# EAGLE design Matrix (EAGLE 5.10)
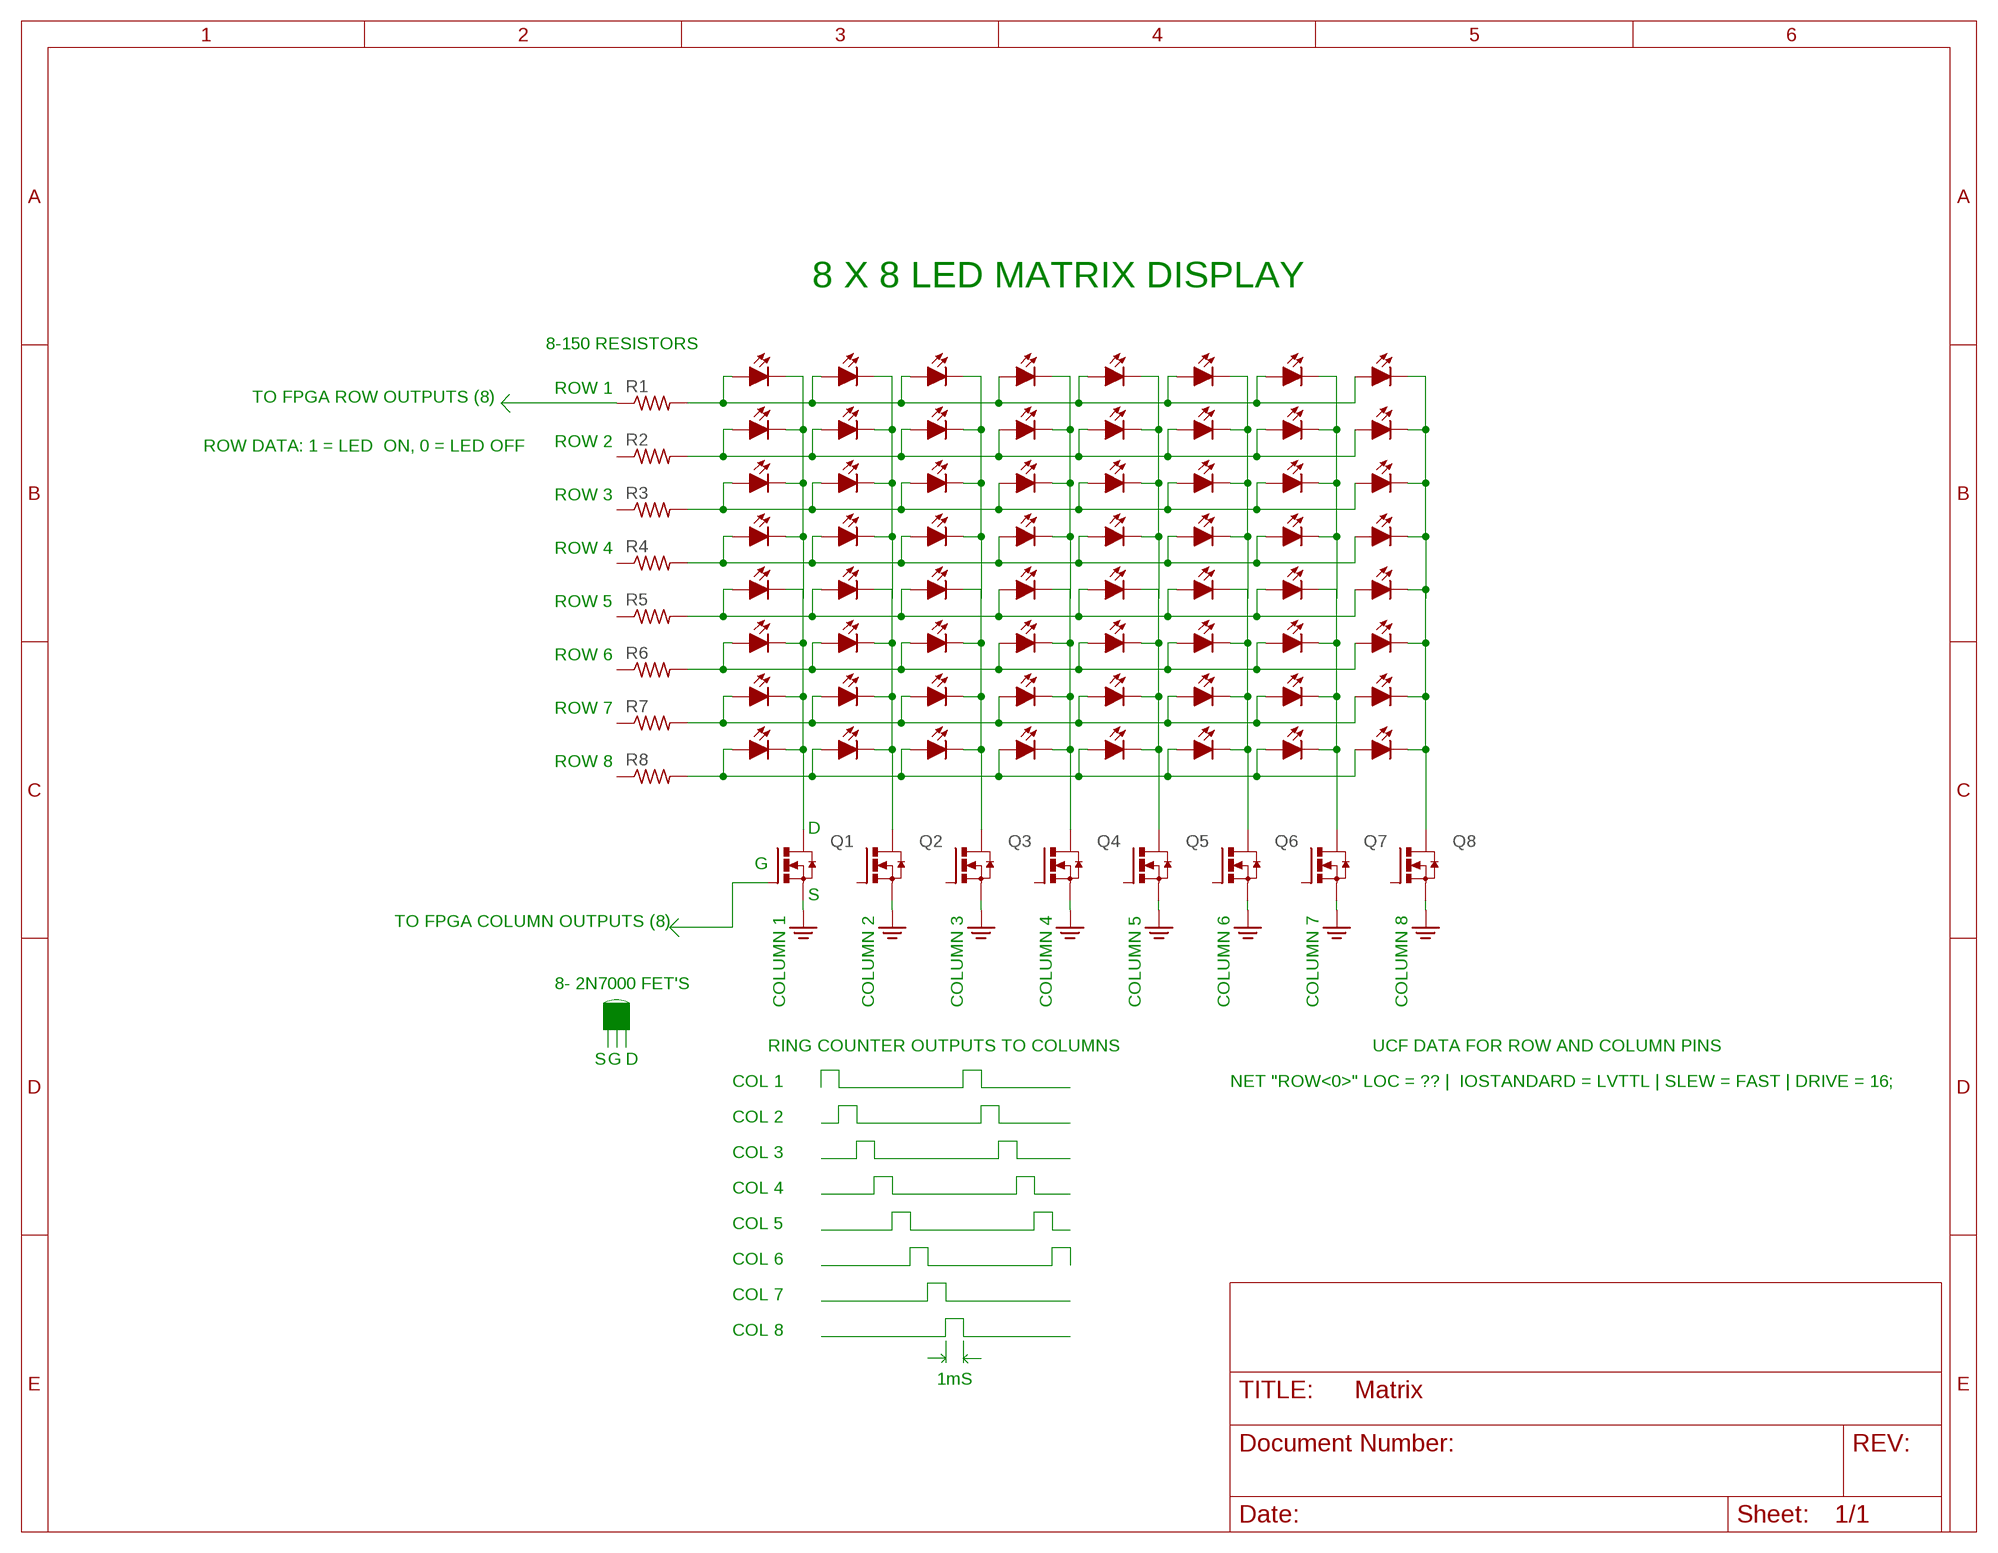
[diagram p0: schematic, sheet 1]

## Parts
D1  LED_ANGLE  [RES_400]
D2  LED_ANGLE  [RES_400]
D3  LED_ANGLE  [RES_400]
D4  LED_ANGLE  [RES_400]
D5  LED_ANGLE  [RES_400]
D6  LED_ANGLE  [RES_400]
D7  LED_ANGLE  [RES_400]
D8  LED_ANGLE  [RES_400]
D9  LED_ANGLE  [RES_400]
D10  LED_ANGLE  [RES_400]
D11  LED_ANGLE  [RES_400]
D12  LED_ANGLE  [RES_400]
D13  LED_ANGLE  [RES_400]
D14  LED_ANGLE  [RES_400]
D15  LED_ANGLE  [RES_400]
D16  LED_ANGLE  [RES_400]
D17  LED_ANGLE  [RES_400]
D18  LED_ANGLE  [RES_400]
D19  LED_ANGLE  [RES_400]
D20  LED_ANGLE  [RES_400]
D21  LED_ANGLE  [RES_400]
D22  LED_ANGLE  [RES_400]
D23  LED_ANGLE  [RES_400]
D24  LED_ANGLE  [RES_400]
D25  LED_ANGLE  [RES_400]
D26  LED_ANGLE  [RES_400]
D27  LED_ANGLE  [RES_400]
D28  LED_ANGLE  [RES_400]
D29  LED_ANGLE  [RES_400]
D30  LED_ANGLE  [RES_400]
D31  LED_ANGLE  [RES_400]
D32  LED_ANGLE  [RES_400]
D33  LED_ANGLE  [RES_400]
D34  LED_ANGLE  [RES_400]
D35  LED_ANGLE  [RES_400]
D36  LED_ANGLE  [RES_400]
D37  LED_ANGLE  [RES_400]
D38  LED_ANGLE  [RES_400]
D39  LED_ANGLE  [RES_400]
D40  LED_ANGLE  [RES_400]
D41  LED_ANGLE  [RES_400]
D42  LED_ANGLE  [RES_400]
D43  LED_ANGLE  [RES_400]
D44  LED_ANGLE  [RES_400]
D45  LED_ANGLE  [RES_400]
D46  LED_ANGLE  [RES_400]
D47  LED_ANGLE  [RES_400]
D48  LED_ANGLE  [RES_400]
D49  LED_ANGLE  [RES_400]
D50  LED_ANGLE  [RES_400]
D51  LED_ANGLE  [RES_400]
D52  LED_ANGLE  [RES_400]
D53  LED_ANGLE  [RES_400]
D54  LED_ANGLE  [RES_400]
D55  LED_ANGLE  [RES_400]
D56  LED_ANGLE  [RES_400]
D57  LED_ANGLE  [RES_400]
D58  LED_ANGLE  [RES_400]
D59  LED_ANGLE  [RES_400]
D60  LED_ANGLE  [RES_400]
D61  LED_ANGLE  [RES_400]
D62  LED_ANGLE  [RES_400]
D63  LED_ANGLE  [RES_400]
D64  LED_ANGLE  [RES_400]
Q1  N-HEXFET_SOT323-IRLL2705  [SOT223]
Q2  N-HEXFET_SOT323-IRLL2705  [SOT223]
Q3  N-HEXFET_SOT323-IRLL2705  [SOT223]
Q4  N-HEXFET_SOT323-IRLL2705  [SOT223]
Q5  N-HEXFET_SOT323-IRLL2705  [SOT223]
Q6  N-HEXFET_SOT323-IRLL2705  [SOT223]
Q7  N-HEXFET_SOT323-IRLL2705  [SOT223]
Q8  N-HEXFET_SOT323-IRLL2705  [SOT223]
R1  R-US_0204/2V  [0204V]
R2  R-US_0204/2V  [0204V]
R3  R-US_0204/2V  [0204V]
R4  R-US_0204/2V  [0204V]
R5  R-US_0204/2V  [0204V]
R6  R-US_0204/2V  [0204V]
R7  R-US_0204/2V  [0204V]
R8  R-US_0204/2V  [0204V]

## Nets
N$67: D1.2(C) D5.2(C) D9.2(C) D13.2(C) Q1.4(D)
N$68: D2.2(C) D6.2(C) D10.2(C) D14.2(C) Q2.4(D)
N$69: D3.2(C) D7.2(C) D11.2(C) D15.2(C) Q3.4(D)
N$70: D4.2(C) D8.2(C) D12.2(C) D16.2(C) Q4.4(D)
N$71: R1.1
N$72: Q1.1(G)
N$75: D17.2(C) D21.2(C) D25.2(C) D29.2(C) Q5.4(D)
N$76: D18.2(C) D22.2(C) D26.2(C) D30.2(C) Q6.4(D)
N$77: D19.2(C) D23.2(C) D27.2(C) D31.2(C) Q7.4(D)
N$78: D24.2(C) D28.2(C) D32.2(C) Q8.4(D)
N$79: D1.1(A) D2.1(A) D3.1(A) D4.1(A) D17.1(A) D18.1(A) D19.1(A) D20.1(A) R5.2
N$80: D5.1(A) D6.1(A) D7.1(A) D8.1(A) D21.1(A) D22.1(A) D23.1(A) D24.1(A) R6.2
N$81: D9.1(A) D10.1(A) D11.1(A) D12.1(A) D25.1(A) D26.1(A) D27.1(A) D28.1(A) R7.2
N$82: D13.1(A) D14.1(A) D15.1(A) D16.1(A) D29.1(A) D30.1(A) D31.1(A) D32.1(A) R8.2
N$83: D33.2(C) D37.2(C) D41.2(C) D45.2(C)
N$84: D34.2(C) D38.2(C) D42.2(C) D46.2(C)
N$85: D35.2(C) D39.2(C) D43.2(C) D47.2(C)
N$86: D36.2(C) D40.2(C) D44.2(C) D48.2(C)
N$91: D49.2(C) D53.2(C) D57.2(C) D61.2(C)
N$92: D50.2(C) D54.2(C) D58.2(C) D62.2(C)
N$93: D51.2(C) D55.2(C) D59.2(C) D63.2(C)
N$94: D20.2(C) D52.2(C) D56.2(C) D60.2(C) D64.2(C)
N$95: D33.1(A) D34.1(A) D35.1(A) D36.1(A) D49.1(A) D50.1(A) D51.1(A) D52.1(A) R1.2
N$96: D37.1(A) D38.1(A) D39.1(A) D40.1(A) D53.1(A) D54.1(A) D55.1(A) D56.1(A) R2.2
N$97: D41.1(A) D42.1(A) D43.1(A) D44.1(A) D57.1(A) D58.1(A) D59.1(A) D60.1(A) R3.2
N$98: D45.1(A) D46.1(A) D47.1(A) D48.1(A) D61.1(A) D62.1(A) D63.1(A) D64.1(A) R4.2
PE: Q1.3(S) Q2.3(S) Q3.3(S) Q4.3(S) Q5.3(S) Q6.3(S) Q7.3(S) Q8.3(S)
Unconnected: Q2.1(G) Q3.1(G) Q4.1(G) Q5.1(G) Q6.1(G) Q7.1(G) Q8.1(G) R2.1 R3.1 R4.1 R5.1 R6.1 R7.1 R8.1

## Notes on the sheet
- 8 X 8 LED MATRIX DISPLAY
- 8-150 RESISTORS
- ROW 1
- TO FPGA ROW OUTPUTS (8)
- ROW DATA: 1 = LED  ON, 0 = LED OFF | ROW 2
- ROW 3
- ROW 4
- ROW 5
- ROW 6
- ROW 7
- ROW 8
- D
- G
- S
- TO FPGA COLUMN OUTPUTS (8)
- 8- 2N7000 FET'S
- COLUMN 1 | COLUMN 2 | COLUMN 3 | COLUMN 4 | COLUMN 5 | COLUMN 6 | COLUMN 7 | COLUMN 8
- RING COUNTER OUTPUTS TO COLUMNS | UCF DATA FOR ROW AND COLUMN PINS
- S | G | D
- COL 1 | NET "ROW<0>" LOC = ?? |  IOSTANDARD = LVTTL | SLEW = FAST | DRIVE = 16;
- COL 2
- COL 3
- COL 4
- COL 5
- COL 6
- COL 7
- COL 8
- 1mS

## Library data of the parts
D1-D64 = led_matrix:LED_ANGLE
Q1-Q8 = transistor-power:N-HEXFET_?-*: HEXFET® Power MOSFET
R1-R8 = rcl:R-US_: RESISTOR, American symbol

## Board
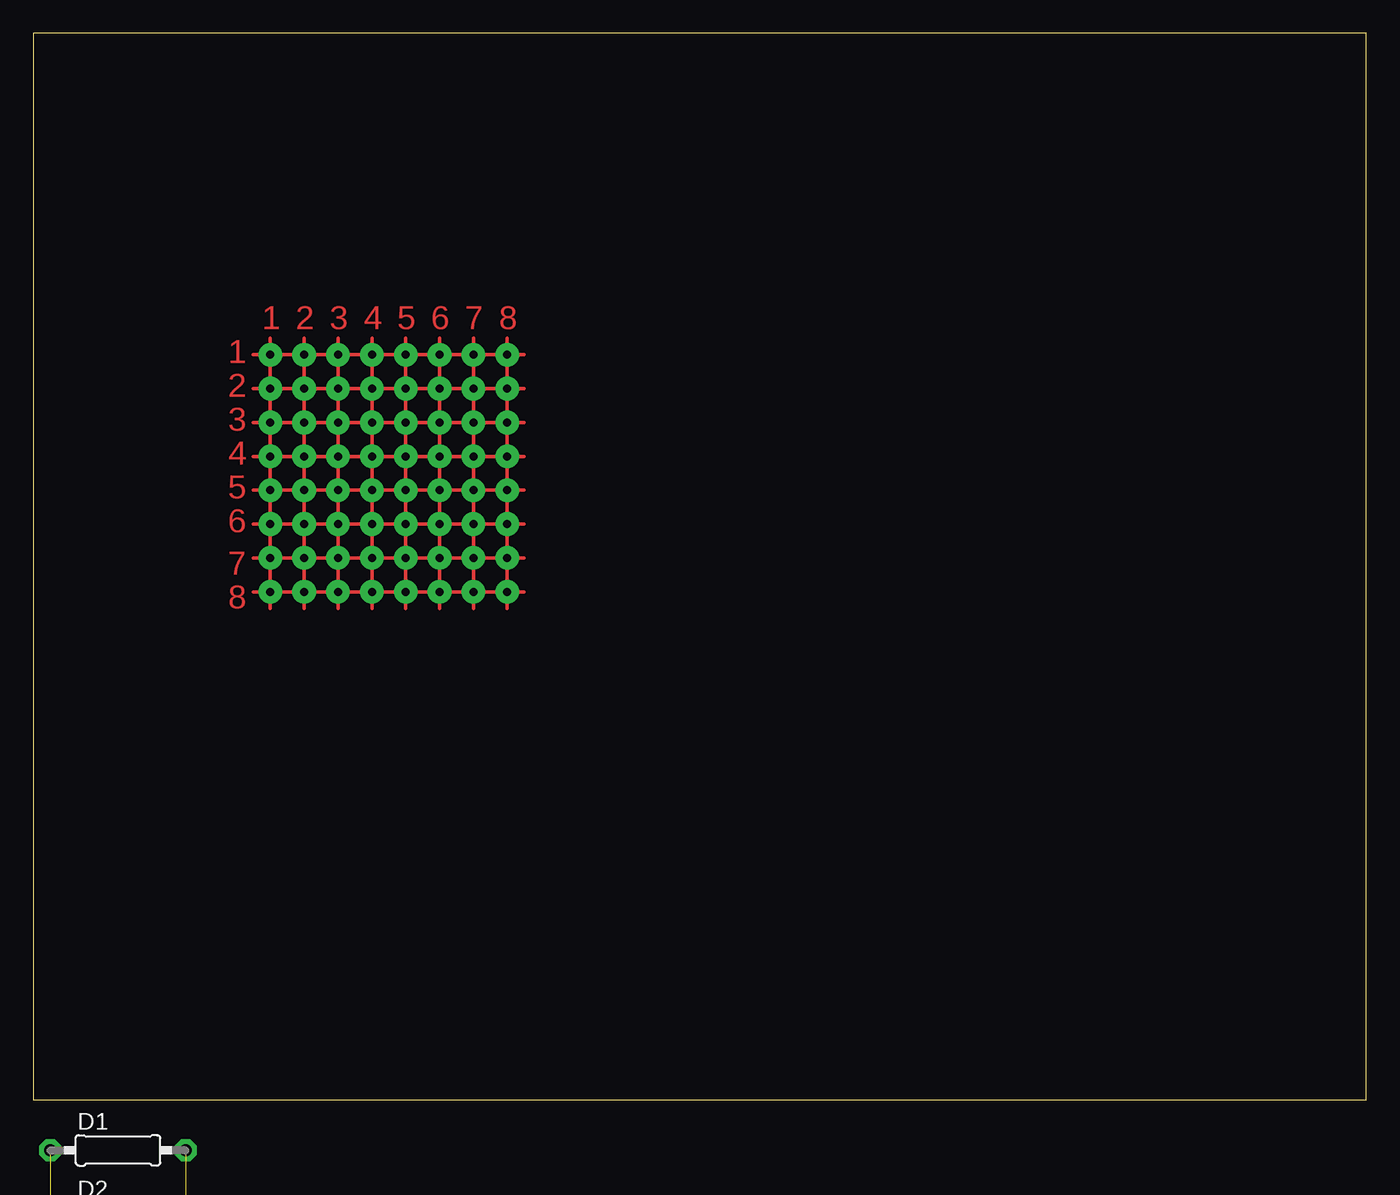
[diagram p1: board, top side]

Size 100 x 80 mm. Coordinates in mm from the lower left corner, seen from the top.
Outline: 0,0 100,0 100,80 0,80 0,0
Copper layers (1*16): Top 0.035mm / dielectric 1.5mm / Bottom 0.035mm
Design rules "default": minimum track width 10mil, minimum drill 24mil, track to track 8mil, track to pad 8mil, pad to pad 8mil, via to via 8mil, smd to smd 8mil, copper to edge 40mil, drill to drill 8mil, minimum pad ring 10mil, minimum via ring 8mil, stop-mask expansion 4mil, vias tented up to drill 0mil, thermal gap 10mil

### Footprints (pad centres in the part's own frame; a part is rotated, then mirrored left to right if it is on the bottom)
RES_400 = drill 0.9 pad 1.676 octagon: 1 0,0; 2 10.16,0
SOT223 = smd 1.219 x 2.235: 1 -2.311,-3.099; 2 0,-3.099; 3 2.311,-3.099 | smd 3.6 x 2.2: 4 0,3.099
0204V = drill 0.813 octagon: 1 -1.27,0; 2 1.27,0

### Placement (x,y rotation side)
D1  not placed on the board
D2  not placed on the board
D3  not placed on the board
D4  not placed on the board
D5  not placed on the board
D6  not placed on the board
D7  not placed on the board
D8  not placed on the board
D9  not placed on the board
D10  not placed on the board
D11  not placed on the board
D12  not placed on the board
D13  not placed on the board
D14  not placed on the board
D15  not placed on the board
D16  not placed on the board
D17  not placed on the board
D18  not placed on the board
D19  not placed on the board
D20  not placed on the board
D21  not placed on the board
D22  not placed on the board
D23  not placed on the board
D24  not placed on the board
D25  not placed on the board
D26  not placed on the board
D27  not placed on the board
D28  not placed on the board
D29  not placed on the board
D30  not placed on the board
D31  not placed on the board
D32  not placed on the board
D33  not placed on the board
D34  not placed on the board
D35  not placed on the board
D36  not placed on the board
D37  not placed on the board
D38  not placed on the board
D39  not placed on the board
D40  not placed on the board
D41  not placed on the board
D42  not placed on the board
D43  not placed on the board
D44  not placed on the board
D45  not placed on the board
D46  not placed on the board
D47  not placed on the board
D48  not placed on the board
D49  not placed on the board
D50  not placed on the board
D51  not placed on the board
D52  not placed on the board
D53  not placed on the board
D54  not placed on the board
D55  not placed on the board
D56  not placed on the board
D57  not placed on the board
D58  not placed on the board
D59  not placed on the board
D60  not placed on the board
D61  not placed on the board
D62  not placed on the board
D63  not placed on the board
D64  not placed on the board
Q1  not placed on the board
Q2  not placed on the board
Q3  not placed on the board
Q4  not placed on the board
Q5  not placed on the board
Q6  not placed on the board
Q7  not placed on the board
Q8  not placed on the board
R1  not placed on the board
R2  not placed on the board
R3  not placed on the board
R4  not placed on the board
R5  not placed on the board
R6  not placed on the board
R7  not placed on the board
R8  not placed on the board

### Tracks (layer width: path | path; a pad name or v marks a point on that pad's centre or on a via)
N$1  (via drill 0.6 pad 1.78)
  other vias: 17.78,55.88
N$2  (via drill 0.6 pad 1.78)
  other vias: 20.32,55.88
N$3  (via drill 0.6 pad 1.78)
  other vias: 22.86,55.88
N$4  (via drill 0.6 pad 1.78)
  other vias: 25.4,55.88
N$5  (via drill 0.6 pad 1.78)
  other vias: 27.94,55.88
N$6  (via drill 0.6 pad 1.78)
  other vias: 30.48,55.88
N$7  (via drill 0.6 pad 1.78)
  other vias: 33.02,55.88
N$8  (via drill 0.6 pad 1.78)
  other vias: 35.56,55.88
N$9  (via drill 0.6 pad 1.78)
  other vias: 17.78,53.34
N$10  (via drill 0.6 pad 1.78)
  other vias: 20.32,53.34
N$11  (via drill 0.6 pad 1.78)
  other vias: 22.86,53.34
N$12  (via drill 0.6 pad 1.78)
  other vias: 25.4,53.34
N$13  (via drill 0.6 pad 1.78)
  other vias: 27.94,53.34
N$14  (via drill 0.6 pad 1.78)
  other vias: 30.48,53.34
N$15  (via drill 0.6 pad 1.78)
  other vias: 33.02,53.34
N$16  (via drill 0.6 pad 1.78)
  other vias: 35.56,53.34
N$17  (via drill 0.6 pad 1.78)
  other vias: 17.78,50.8
N$18  (via drill 0.6 pad 1.78)
  other vias: 20.32,50.8
N$19  (via drill 0.6 pad 1.78)
  other vias: 22.86,50.8
N$20  (via drill 0.6 pad 1.78)
  other vias: 25.4,50.8
N$21  (via drill 0.6 pad 1.78)
  other vias: 27.94,50.8
N$22  (via drill 0.6 pad 1.78)
  other vias: 30.48,50.8
N$23  (via drill 0.6 pad 1.78)
  other vias: 33.02,50.8
N$24  (via drill 0.6 pad 1.78)
  other vias: 35.56,50.8
N$25  (via drill 0.6 pad 1.78)
  other vias: 17.78,48.26
N$26  (via drill 0.6 pad 1.78)
  other vias: 20.32,48.26
N$27  (via drill 0.6 pad 1.78)
  other vias: 22.86,48.26
N$28  (via drill 0.6 pad 1.78)
  other vias: 25.4,48.26
N$29  (via drill 0.6 pad 1.78)
  other vias: 27.94,48.26
N$30  (via drill 0.6 pad 1.78)
  other vias: 30.48,48.26
N$31  (via drill 0.6 pad 1.78)
  other vias: 33.02,48.26
N$32  (via drill 0.6 pad 1.78)
  other vias: 35.56,48.26
N$33  (via drill 0.6 pad 1.78)
  other vias: 17.78,45.72
N$34  (via drill 0.6 pad 1.78)
  other vias: 20.32,45.72
N$35  (via drill 0.6 pad 1.78)
  other vias: 22.86,45.72
N$36  (via drill 0.6 pad 1.78)
  other vias: 25.4,45.72
N$37  (via drill 0.6 pad 1.78)
  other vias: 27.94,45.72
N$38  (via drill 0.6 pad 1.78)
  other vias: 30.48,45.72
N$39  (via drill 0.6 pad 1.78)
  other vias: 33.02,45.72
N$40  (via drill 0.6 pad 1.78)
  other vias: 35.56,45.72
N$41  (via drill 0.6 pad 1.78)
  other vias: 17.78,43.18
N$42  (via drill 0.6 pad 1.78)
  other vias: 20.32,43.18
N$43  (via drill 0.6 pad 1.78)
  other vias: 22.86,43.18
N$44  (via drill 0.6 pad 1.78)
  other vias: 25.4,43.18
N$45  (via drill 0.6 pad 1.78)
  other vias: 27.94,43.18
N$46  (via drill 0.6 pad 1.78)
  other vias: 30.48,43.18
N$47  (via drill 0.6 pad 1.78)
  other vias: 33.02,43.18
N$48  (via drill 0.6 pad 1.78)
  other vias: 35.56,43.18
N$49  (via drill 0.6 pad 1.78)
  other vias: 17.78,40.64
N$50  (via drill 0.6 pad 1.78)
  other vias: 20.32,40.64
N$51  (via drill 0.6 pad 1.78)
  other vias: 22.86,40.64
N$52  (via drill 0.6 pad 1.78)
  other vias: 25.4,40.64
N$53  (via drill 0.6 pad 1.78)
  other vias: 27.94,40.64
N$54  (via drill 0.6 pad 1.78)
  other vias: 30.48,40.64
N$55  (via drill 0.6 pad 1.78)
  other vias: 33.02,40.64
N$56  (via drill 0.6 pad 1.78)
  other vias: 35.56,40.64
N$57  (via drill 0.6 pad 1.78)
  other vias: 17.78,38.1
N$58  (via drill 0.6 pad 1.78)
  other vias: 20.32,38.1
N$59  (via drill 0.6 pad 1.78)
  other vias: 22.86,38.1
N$60  (via drill 0.6 pad 1.78)
  other vias: 25.4,38.1
N$61  (via drill 0.6 pad 1.78)
  other vias: 27.94,38.1
N$62  (via drill 0.6 pad 1.78)
  other vias: 30.48,38.1
N$63  (via drill 0.6 pad 1.78)
  other vias: 33.02,38.1
N$64  (via drill 0.6 pad 1.78)
  other vias: 35.56,38.1
N$65
  Top 0.254: 16.51,55.88 36.83,55.88 | 16.51,53.34 36.83,53.34 | 16.51,50.8 36.83,50.8 | 16.51,48.26 36.83,48.26 | 16.51,45.72 36.83,45.72 | 16.51,43.18 36.83,43.18 | 16.51,40.64 36.83,40.64 | 16.51,38.1 36.83,38.1
N$66
  Top 0.254: 17.78,57.15 17.78,36.83 | 20.32,57.15 20.32,36.83 | 22.86,57.15 22.86,36.83 | 25.4,57.15 25.4,36.83 | 27.94,57.15 27.94,36.83 | 30.48,57.15 30.48,36.83 | 33.02,57.15 33.02,36.83 | 35.56,57.15 35.56,36.83
N$67  (4 unrouted)
N$68  (4 unrouted)
N$69  (4 unrouted)
N$70  (4 unrouted)
N$75  (4 unrouted)
N$76  (4 unrouted)
N$77  (4 unrouted)
N$78  (3 unrouted)
N$79  (8 unrouted)
N$80  (8 unrouted)
N$81  (8 unrouted)
N$82  (8 unrouted)
N$83  (3 unrouted)
N$84  (3 unrouted)
N$85  (3 unrouted)
N$86  (3 unrouted)
N$91  (3 unrouted)
N$92  (3 unrouted)
N$93  (3 unrouted)
N$94  (4 unrouted)
N$95  (8 unrouted)
N$96  (8 unrouted)
N$97  (8 unrouted)
N$98  (8 unrouted)
PE  (7 unrouted)

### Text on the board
Top: 1 | 2 | 3 | 4 | 5 | 6 | 7 | 8 | 1 | 2 | 3 | 4 | 5 | 6 | 7 | 8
